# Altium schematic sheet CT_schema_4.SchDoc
size 176 x 147 mm
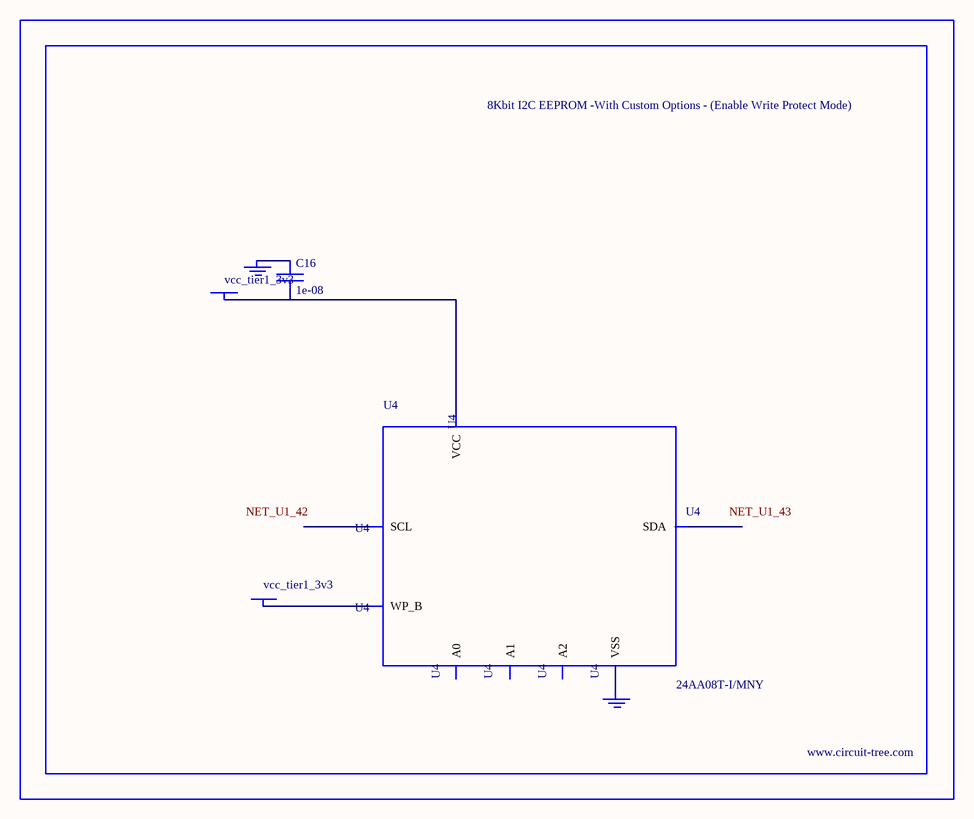
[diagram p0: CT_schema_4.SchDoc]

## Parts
BORDER3  (no value)
C16  1e-08  [C0402]
GND_INSTANCE_3_0  (no value)
GND_INSTANCE_3_1  (no value)
POWER_INSTANCE_3_0  vcc_tier1_3v3
POWER_INSTANCE_3_1  vcc_tier1_3v3
U4  24AA08T-I/MNY  [TDFN-8/6MM]

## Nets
NetC16_1: C16.1 GND_INSTANCE_3_0.0(GND)
NetC16_2: C16.2 POWER_INSTANCE_3_1.0(PWR) U4.8(VCC)
NetGND_INSTANCE_3_1_0: GND_INSTANCE_3_1.0(GND) U4.4(VSS)
NetPOWER_INSTANCE_3_0_0: POWER_INSTANCE_3_0.0(PWR) U4.7(WP_B)

Not connected (* = marked no-connect by the designer): U4 1(A0) 2(A1) 3(A2) 5(SDA) 6(SCL)

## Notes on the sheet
- Labels drawn without touching a wire or pin: NET_U1_42, NET_U1_43

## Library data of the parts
BORDER3 = BORDER_PAGE3
C16 = C0402C103K3RAC
GND_INSTANCE_3_0 GND_INSTANCE_3_1 = GND
POWER_INSTANCE_3_0 POWER_INSTANCE_3_1 = PWR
